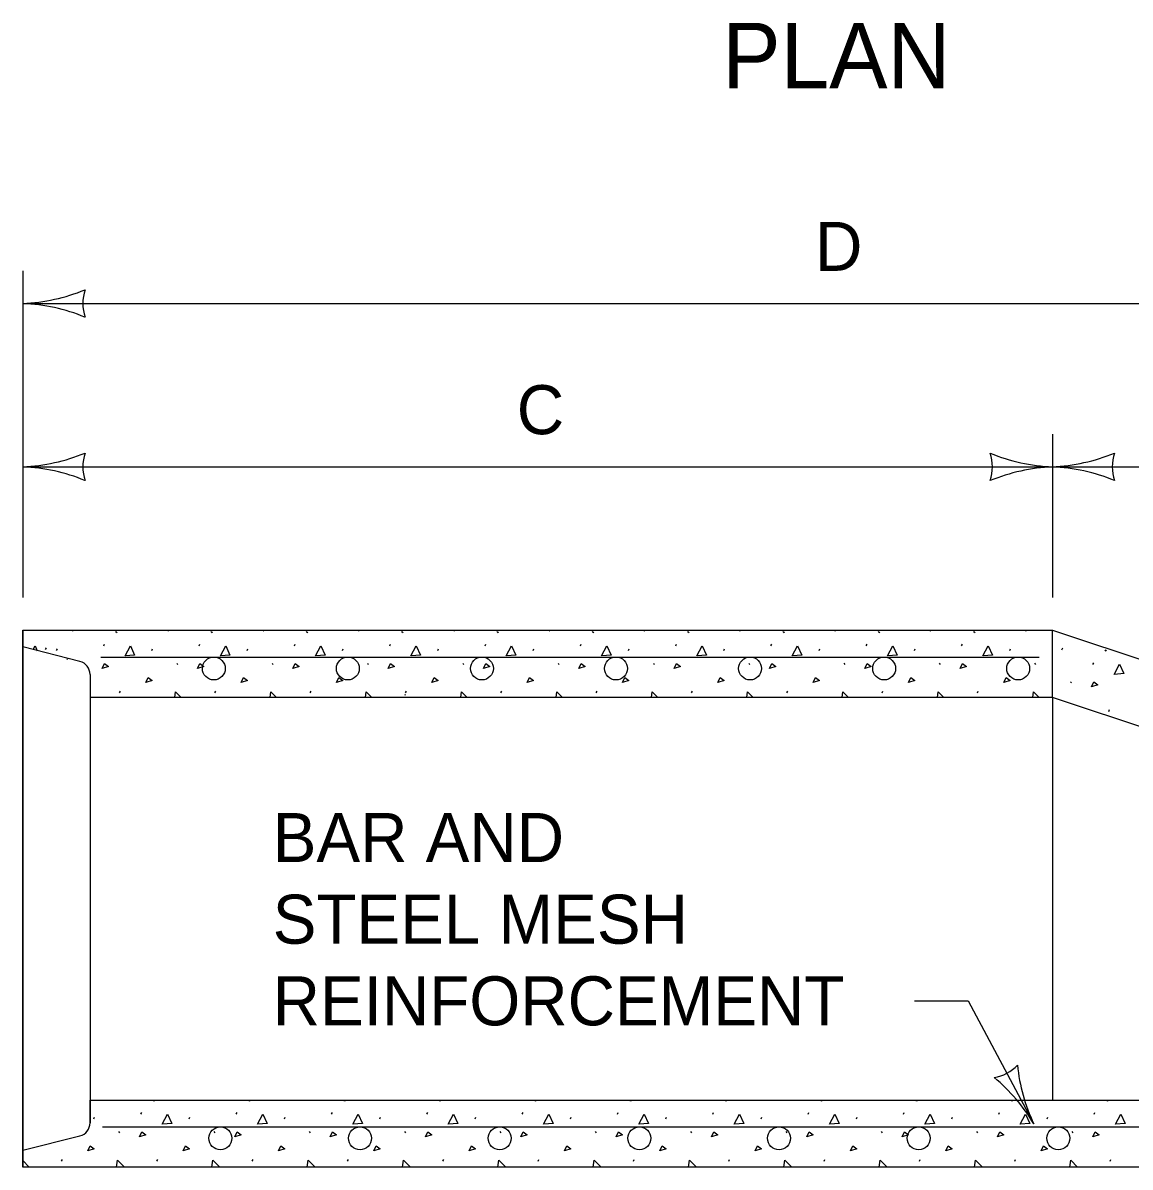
# Model space of a CAD drawing. Extents: x 49991.4 to 50022.1, y 49985 to 50011.4.
# Drawn here: x 50009.608 to 50010.964, y 49995.4 to 49996.801 of the extents above; entities that cross this region are included whole.
import ezdxf

# ---------------------------------------------------------------- set-up
doc = ezdxf.new("R2010")
doc.units = 0
for name, color, linetype in [('Level 1', 7, 'Continuous'), ('Level 2', 7, 'Continuous'), ('Level 3', 7, 'Continuous')]:
    doc.layers.add(name, color=color, linetype=linetype)

msp = doc.modelspace()

# ---------------------------------------------------------------- linework, layer by layer
at = {"layer": 'Level 1'}
for p, q in [((50009.6084, 49996.0573), (50010.8686, 49996.0573)), ((50009.6084, 49996.0573), (50009.6084, 49995.3998)), ((50009.6084, 49995.3998), (50009.6084, 49996.0573)), ((50009.6084, 49995.4204), (50009.6084, 49996.0573)), ((50009.6693, 49996.0561), (50009.6698, 49996.0573)), ((50009.7217, 49996.0561), (50009.7227, 49996.0546)), ((50009.7227, 49996.0555), (50009.7236, 49996.0541)), ((50009.786, 49996.0561), (50009.7865, 49996.0573)), ((50009.8384, 49996.0561), (50009.8394, 49996.0546)), ((50009.8394, 49996.0555), (50009.8403, 49996.0541)), ((50009.9027, 49996.0561), (50009.9032, 49996.0573)), ((50009.9551, 49996.0561), (50009.956, 49996.0546)), ((50009.956, 49996.0555), (50009.957, 49996.0541)), ((50010.0194, 49996.0561), (50010.0199, 49996.0573)), ((50010.0718, 49996.0561), (50010.0727, 49996.0546)), ((50010.0727, 49996.0555), (50010.0737, 49996.0541)), ((50010.1361, 49996.0561), (50010.1366, 49996.0573)), ((50010.1884, 49996.0561), (50010.1894, 49996.0546)), ((50010.1894, 49996.0555), (50010.1904, 49996.0541)), ((50010.2528, 49996.0561), (50010.2533, 49996.0573)), ((50010.3051, 49996.0561), (50010.3061, 49996.0546)), ((50010.3061, 49996.0555), (50010.3071, 49996.0541)), ((50010.3694, 49996.0561), (50010.3699, 49996.0573)), ((50010.4218, 49996.0561), (50010.4228, 49996.0546)), ((50010.4228, 49996.0555), (50010.4238, 49996.0541)), ((50010.4861, 49996.0561), (50010.4866, 49996.0573)), ((50010.5385, 49996.0561), (50010.5395, 49996.0546)), ((50010.5395, 49996.0555), (50010.5405, 49996.0541)), ((50010.6028, 49996.0561), (50010.6033, 49996.0573)), ((50010.6552, 49996.0561), (50010.6562, 49996.0546)), ((50010.6562, 49996.0555), (50010.6572, 49996.0541)), ((50010.7195, 49996.0561), (50010.72, 49996.0573)), ((50010.7719, 49996.0561), (50010.7729, 49996.0546)), ((50010.7729, 49996.0555), (50010.7738, 49996.0541)), ((50010.8362, 49996.0561), (50010.8367, 49996.0573)), ((50010.8686, 49996.0573), (50011.5522, 49995.8295)), ((50010.8686, 49995.975), (50010.8686, 49996.0573)), ((50009.6782, 49996.019), (50009.6084, 49996.0367)), ((50009.6362, 49996.0335), (50009.6372, 49996.0357)), ((50009.6496, 49996.0324), (50009.6506, 49996.0346)), ((50009.7073, 49996.038), (50009.7083, 49996.0402)), ((50009.7663, 49996.0324), (50009.7672, 49996.0346)), ((50009.824, 49996.038), (50009.825, 49996.0402)), ((50009.883, 49996.0324), (50009.8839, 49996.0346)), ((50009.9407, 49996.038), (50009.9417, 49996.0402)), ((50009.9996, 49996.0324), (50010.0006, 49996.0346)), ((50010.0574, 49996.038), (50010.0584, 49996.0402)), ((50010.1163, 49996.0324), (50010.1173, 49996.0346)), ((50010.1741, 49996.038), (50010.175, 49996.0402)), ((50010.233, 49996.0324), (50010.234, 49996.0346)), ((50010.2908, 49996.038), (50010.2917, 49996.0402)), ((50010.3497, 49996.0324), (50010.3507, 49996.0346)), ((50010.4075, 49996.038), (50010.4084, 49996.0402)), ((50010.4664, 49996.0324), (50010.4674, 49996.0346)), ((50010.5241, 49996.038), (50010.5251, 49996.0402)), ((50010.5831, 49996.0324), (50010.5841, 49996.0346)), ((50010.6408, 49996.038), (50010.6418, 49996.0402)), ((50010.6998, 49996.0324), (50010.7008, 49996.0346)), ((50010.7575, 49996.038), (50010.7585, 49996.0402)), ((50010.8165, 49996.0324), (50010.8174, 49996.0346)), ((50010.8803, 49996.0334), (50010.8813, 49996.0356)), ((50010.9327, 49996.0334), (50010.9336, 49996.0319)), ((50010.9336, 49996.0328), (50010.9346, 49996.0314)), ((50009.6778, 49996.0193), (50009.678, 49996.019)), ((50009.7967, 49996.0169), (50009.7977, 49996.0154)), ((50009.9134, 49996.0169), (50009.9144, 49996.0154)), ((50010.0301, 49996.0169), (50010.0311, 49996.0154)), ((50010.1468, 49996.0169), (50010.1478, 49996.0154)), ((50010.2635, 49996.0169), (50010.2645, 49996.0154)), ((50010.3802, 49996.0169), (50010.3811, 49996.0154)), ((50010.4969, 49996.0169), (50010.4978, 49996.0154)), ((50010.6135, 49996.0169), (50010.6145, 49996.0154)), ((50010.7302, 49996.0169), (50010.7312, 49996.0154)), ((50010.8469, 49996.0169), (50010.8479, 49996.0154)), ((50010.9183, 49996.0153), (50010.9193, 49996.0175)), ((50009.6906, 49996.0031), (50009.6906, 49995.454)), ((50010.891, 49995.9941), (50010.892, 49995.9927)), ((50009.7268, 49995.9806), (50009.7278, 49995.9827)), ((50009.8435, 49995.9806), (50009.8445, 49995.9827)), ((50009.9602, 49995.9806), (50009.9612, 49995.9827)), ((50010.0758, 49995.9788), (50010.0765, 49995.9778)), ((50010.0769, 49995.9806), (50010.0778, 49995.9827)), ((50010.1936, 49995.9806), (50010.1945, 49995.9827)), ((50010.3103, 49995.9806), (50010.3112, 49995.9827)), ((50010.4269, 49995.9806), (50010.4279, 49995.9827)), ((50010.5436, 49995.9806), (50010.5446, 49995.9827)), ((50010.6603, 49995.9806), (50010.6613, 49995.9827)), ((50010.777, 49995.9806), (50010.778, 49995.9827)), ((50010.8686, 49995.975), (50009.6906, 49995.975)), ((50011.5634, 49995.7435), (50010.8686, 49995.975)), ((50010.8686, 49995.975), (50010.8686, 49995.4819)), ((50010.9378, 49995.9578), (50010.9387, 49995.96)), ((50009.6906, 49995.4819), (50011.6084, 49995.4819)), ((50009.6906, 49995.454), (50009.6906, 49995.4819)), ((50009.7678, 49995.4819), (50009.7683, 49995.4811)), ((50009.7683, 49995.482), (50009.7692, 49995.4806)), ((50009.8845, 49995.4819), (50009.885, 49995.4811)), ((50009.885, 49995.482), (50009.8859, 49995.4806)), ((50010.0012, 49995.4819), (50010.0017, 49995.4811)), ((50010.0017, 49995.482), (50010.0026, 49995.4806)), ((50010.1178, 49995.4819), (50010.1183, 49995.4811)), ((50010.1183, 49995.482), (50010.1193, 49995.4806)), ((50010.2345, 49995.4819), (50010.235, 49995.4811)), ((50010.235, 49995.482), (50010.236, 49995.4806)), ((50010.3512, 49995.4819), (50010.3517, 49995.4811)), ((50010.3517, 49995.482), (50010.3527, 49995.4806)), ((50010.4679, 49995.4819), (50010.4684, 49995.4811)), ((50010.4684, 49995.482), (50010.4694, 49995.4806)), ((50010.5846, 49995.4819), (50010.5851, 49995.4811)), ((50010.5851, 49995.482), (50010.5861, 49995.4806)), ((50010.7013, 49995.4819), (50010.7018, 49995.4811)), ((50010.7018, 49995.482), (50010.7028, 49995.4806)), ((50010.818, 49995.4819), (50010.8185, 49995.4811)), ((50010.8185, 49995.482), (50010.8195, 49995.4806)), ((50010.9347, 49995.4819), (50010.9352, 49995.4811)), ((50010.9352, 49995.482), (50010.9361, 49995.4806)), ((50009.6952, 49995.4589), (50009.6962, 49995.4611)), ((50009.7529, 49995.4645), (50009.7539, 49995.4667)), ((50009.8119, 49995.4589), (50009.8129, 49995.4611)), ((50009.8696, 49995.4645), (50009.8706, 49995.4667)), ((50009.9286, 49995.4589), (50009.9295, 49995.4611)), ((50009.9863, 49995.4645), (50009.9873, 49995.4667)), ((50010.0453, 49995.4589), (50010.0462, 49995.4611)), ((50010.103, 49995.4645), (50010.104, 49995.4667)), ((50010.1619, 49995.4589), (50010.1629, 49995.4611)), ((50010.2197, 49995.4645), (50010.2207, 49995.4667)), ((50010.2786, 49995.4589), (50010.2796, 49995.4611)), ((50010.3364, 49995.4645), (50010.3373, 49995.4667)), ((50010.3953, 49995.4589), (50010.3963, 49995.4611)), ((50010.4531, 49995.4645), (50010.454, 49995.4667)), ((50010.512, 49995.4589), (50010.513, 49995.4611)), ((50010.5698, 49995.4645), (50010.5707, 49995.4667)), ((50010.6287, 49995.4589), (50010.6297, 49995.4611)), ((50010.6864, 49995.4645), (50010.6874, 49995.4667)), ((50010.7454, 49995.4589), (50010.7464, 49995.4611)), ((50010.8031, 49995.4645), (50010.8041, 49995.4667)), ((50010.8621, 49995.4589), (50010.8631, 49995.4611)), ((50010.9198, 49995.4645), (50010.9208, 49995.4667)), ((50009.6084, 49995.4204), (50009.6782, 49995.4381)), ((50009.7256, 49995.4434), (50009.7266, 49995.4419)), ((50009.8423, 49995.4434), (50009.8433, 49995.4419)), ((50009.959, 49995.4434), (50009.96, 49995.4419)), ((50010.0757, 49995.4434), (50010.0767, 49995.4419)), ((50010.1924, 49995.4434), (50010.1934, 49995.4419)), ((50010.3091, 49995.4434), (50010.3101, 49995.4419)), ((50010.4258, 49995.4434), (50010.4268, 49995.4419)), ((50010.5425, 49995.4434), (50010.5434, 49995.4419)), ((50010.6592, 49995.4434), (50010.6601, 49995.4419)), ((50010.7758, 49995.4434), (50010.7768, 49995.4419)), ((50010.8925, 49995.4434), (50010.8935, 49995.4419)), ((50009.6557, 49995.4071), (50009.6567, 49995.4092)), ((50009.7724, 49995.4071), (50009.7734, 49995.4092)), ((50009.8891, 49995.4071), (50009.8901, 49995.4092)), ((50010.0058, 49995.4071), (50010.0068, 49995.4092)), ((50010.1225, 49995.4071), (50010.1235, 49995.4092)), ((50010.2392, 49995.4071), (50010.2401, 49995.4092)), ((50010.3559, 49995.4071), (50010.3568, 49995.4092)), ((50010.4726, 49995.4071), (50010.4735, 49995.4092)), ((50010.5892, 49995.4071), (50010.5902, 49995.4092)), ((50010.7059, 49995.4071), (50010.7069, 49995.4092)), ((50010.8226, 49995.4071), (50010.8236, 49995.4092)), ((50010.9393, 49995.4071), (50010.9403, 49995.4092)), ((50011.6084, 49995.3998), (50009.6084, 49995.3998))]:
    msp.add_line(p, q, dxfattribs=at)
for points in [[(50009.6208, 49996.0336), (50009.6233, 49996.0383), (50009.626, 49996.0322)], [(50009.7334, 49996.0259), (50009.74, 49996.0383), (50009.7451, 49996.0268), (50009.7336, 49996.0259)], [(50009.8501, 49996.0259), (50009.8567, 49996.0383), (50009.8618, 49996.0268), (50009.8503, 49996.0259)], [(50009.9668, 49996.0259), (50009.9733, 49996.0383), (50009.9785, 49996.0268), (50009.967, 49996.0259)], [(50010.0835, 49996.0259), (50010.09, 49996.0383), (50010.0951, 49996.0268), (50010.0837, 49996.0259)], [(50010.2001, 49996.0259), (50010.2067, 49996.0383), (50010.2118, 49996.0268), (50010.2004, 49996.0259)], [(50010.3168, 49996.0259), (50010.3234, 49996.0383), (50010.3285, 49996.0268), (50010.3171, 49996.0259)], [(50010.4335, 49996.0259), (50010.4401, 49996.0383), (50010.4452, 49996.0268), (50010.4338, 49996.0259)], [(50010.5502, 49996.0259), (50010.5568, 49996.0383), (50010.5619, 49996.0268), (50010.5505, 49996.0259)], [(50010.6669, 49996.0259), (50010.6735, 49996.0383), (50010.6786, 49996.0268), (50010.6671, 49996.0259)], [(50010.7836, 49996.0259), (50010.7902, 49996.0383), (50010.7953, 49996.0268), (50010.7838, 49996.0259)], [(50009.6623, 49996.0213), (50009.6625, 49996.0216)], [(50009.6629, 49996.0213), (50009.6625, 49996.0213)], [(50009.7037, 49996.0243), (50010.8526, 49996.0243)], [(50009.7056, 49996.0105), (50009.7085, 49996.0166), (50009.7134, 49996.013), (50009.7056, 49996.0105)], [(50009.8223, 49996.0105), (50009.8252, 49996.0166), (50009.8301, 49996.013), (50009.8223, 49996.0105)], [(50009.939, 49996.0105), (50009.9419, 49996.0166), (50009.9468, 49996.013), (50009.939, 49996.0105)], [(50010.0557, 49996.0105), (50010.0586, 49996.0166), (50010.0635, 49996.013), (50010.0557, 49996.0105)], [(50010.1724, 49996.0105), (50010.1753, 49996.0166), (50010.1802, 49996.013), (50010.1724, 49996.0105)], [(50010.2891, 49996.0105), (50010.292, 49996.0166), (50010.2969, 49996.013), (50010.2891, 49996.0105)], [(50010.4057, 49996.0105), (50010.4087, 49996.0166), (50010.4135, 49996.013), (50010.4057, 49996.0105)], [(50010.5224, 49996.0105), (50010.5254, 49996.0166), (50010.5302, 49996.013), (50010.5224, 49996.0105)], [(50010.6391, 49996.0105), (50010.642, 49996.0166), (50010.6469, 49996.013), (50010.6391, 49996.0105)], [(50010.7558, 49996.0105), (50010.7587, 49996.0166), (50010.7636, 49996.013), (50010.7558, 49996.0105)], [(50010.9444, 49996.0032), (50010.9509, 49996.0156), (50010.956, 49996.0041), (50010.9446, 49996.0032)], [(50009.759, 49995.9931), (50009.7619, 49995.9992), (50009.7668, 49995.9955), (50009.759, 49995.9931)], [(50009.8757, 49995.9931), (50009.8786, 49995.9992), (50009.8835, 49995.9955), (50009.8757, 49995.9931)], [(50009.9924, 49995.9931), (50009.9953, 49995.9992), (50010.0002, 49995.9955), (50009.9924, 49995.9931)], [(50010.1091, 49995.9931), (50010.112, 49995.9992), (50010.1169, 49995.9955), (50010.1091, 49995.9931)], [(50010.2258, 49995.9931), (50010.2287, 49995.9992), (50010.2336, 49995.9955), (50010.2258, 49995.9931)], [(50010.3425, 49995.9931), (50010.3454, 49995.9992), (50010.3503, 49995.9955), (50010.3425, 49995.9931)], [(50010.4591, 49995.9931), (50010.4621, 49995.9992), (50010.4669, 49995.9955), (50010.4591, 49995.9931)], [(50010.5758, 49995.9931), (50010.5788, 49995.9992), (50010.5836, 49995.9955), (50010.5758, 49995.9931)], [(50010.6925, 49995.9931), (50010.6954, 49995.9992), (50010.7003, 49995.9955), (50010.6925, 49995.9931)], [(50010.8092, 49995.9931), (50010.8121, 49995.9992), (50010.817, 49995.9955), (50010.8092, 49995.9931)], [(50010.9166, 49995.9878), (50010.9195, 49995.9939), (50010.9244, 49995.9902), (50010.9166, 49995.9878)], [(50009.7945, 49995.975), (50009.7954, 49995.982), (50009.8022, 49995.975)], [(50009.9112, 49995.975), (50009.9121, 49995.982), (50009.9189, 49995.975)], [(50010.0278, 49995.975), (50010.0288, 49995.982), (50010.0356, 49995.975)], [(50010.1445, 49995.975), (50010.1455, 49995.982), (50010.1523, 49995.975)], [(50010.2612, 49995.975), (50010.2622, 49995.982), (50010.269, 49995.975)], [(50010.3779, 49995.975), (50010.3788, 49995.982), (50010.3856, 49995.975)], [(50010.4946, 49995.975), (50010.4955, 49995.982), (50010.5023, 49995.975)], [(50010.6113, 49995.975), (50010.6122, 49995.982), (50010.619, 49995.975)], [(50010.728, 49995.975), (50010.7289, 49995.982), (50010.7357, 49995.975)], [(50010.8447, 49995.975), (50010.8456, 49995.982), (50010.8524, 49995.975)], [(50009.779, 49995.4524), (50009.7856, 49995.4648), (50009.7907, 49995.4533), (50009.7792, 49995.4524)], [(50009.8957, 49995.4524), (50009.9023, 49995.4648), (50009.9074, 49995.4533), (50009.8959, 49995.4524)], [(50010.0124, 49995.4524), (50010.019, 49995.4648), (50010.0241, 49995.4533), (50010.0126, 49995.4524)], [(50010.1291, 49995.4524), (50010.1356, 49995.4648), (50010.1408, 49995.4533), (50010.1293, 49995.4524)], [(50010.2458, 49995.4524), (50010.2523, 49995.4648), (50010.2574, 49995.4533), (50010.246, 49995.4524)], [(50010.3624, 49995.4524), (50010.369, 49995.4648), (50010.3741, 49995.4533), (50010.3627, 49995.4524)], [(50010.4791, 49995.4524), (50010.4857, 49995.4648), (50010.4908, 49995.4533), (50010.4794, 49995.4524)], [(50010.5958, 49995.4524), (50010.6024, 49995.4648), (50010.6075, 49995.4533), (50010.5961, 49995.4524)], [(50010.7125, 49995.4524), (50010.7191, 49995.4648), (50010.7242, 49995.4533), (50010.7128, 49995.4524)], [(50010.8292, 49995.4524), (50010.8358, 49995.4648), (50010.8409, 49995.4533), (50010.8294, 49995.4524)], [(50010.9459, 49995.4524), (50010.9525, 49995.4648), (50010.9576, 49995.4533), (50010.9461, 49995.4524)], [(50009.706, 49995.4491), (50011.5866, 49995.4491)], [(50009.7512, 49995.437), (50009.7541, 49995.4431), (50009.759, 49995.4395), (50009.7512, 49995.437)], [(50009.8679, 49995.437), (50009.8708, 49995.4431), (50009.8757, 49995.4395), (50009.8679, 49995.437)], [(50009.9846, 49995.437), (50009.9875, 49995.4431), (50009.9924, 49995.4395), (50009.9846, 49995.437)], [(50010.1013, 49995.437), (50010.1042, 49995.4431), (50010.1091, 49995.4395), (50010.1013, 49995.437)], [(50010.218, 49995.437), (50010.2209, 49995.4431), (50010.2258, 49995.4395), (50010.218, 49995.437)], [(50010.3347, 49995.437), (50010.3376, 49995.4431), (50010.3425, 49995.4395), (50010.3347, 49995.437)], [(50010.4514, 49995.437), (50010.4543, 49995.4431), (50010.4592, 49995.4395), (50010.4514, 49995.437)], [(50010.568, 49995.437), (50010.571, 49995.4431), (50010.5758, 49995.4395), (50010.568, 49995.437)], [(50010.6847, 49995.437), (50010.6877, 49995.4431), (50010.6925, 49995.4395), (50010.6847, 49995.437)], [(50010.8014, 49995.437), (50010.8043, 49995.4431), (50010.8092, 49995.4395), (50010.8014, 49995.437)], [(50010.9181, 49995.437), (50010.921, 49995.4431), (50010.9259, 49995.4395), (50010.9181, 49995.437)], [(50009.6879, 49995.4196), (50009.6909, 49995.4257), (50009.6957, 49995.422), (50009.6879, 49995.4196)], [(50009.8046, 49995.4196), (50009.8075, 49995.4257), (50009.8124, 49995.422), (50009.8046, 49995.4196)], [(50009.9213, 49995.4196), (50009.9242, 49995.4257), (50009.9291, 49995.422), (50009.9213, 49995.4196)], [(50010.038, 49995.4196), (50010.0409, 49995.4257), (50010.0458, 49995.422), (50010.038, 49995.4196)], [(50010.1547, 49995.4196), (50010.1576, 49995.4257), (50010.1625, 49995.422), (50010.1547, 49995.4196)], [(50010.2714, 49995.4196), (50010.2743, 49995.4257), (50010.2792, 49995.422), (50010.2714, 49995.4196)], [(50010.3881, 49995.4196), (50010.391, 49995.4257), (50010.3959, 49995.422), (50010.3881, 49995.4196)], [(50010.5048, 49995.4196), (50010.5077, 49995.4257), (50010.5126, 49995.422), (50010.5048, 49995.4196)], [(50010.6214, 49995.4196), (50010.6244, 49995.4257), (50010.6292, 49995.422), (50010.6214, 49995.4196)], [(50010.7381, 49995.4196), (50010.7411, 49995.4257), (50010.7459, 49995.422), (50010.7381, 49995.4196)], [(50010.8548, 49995.4196), (50010.8577, 49995.4257), (50010.8626, 49995.422), (50010.8548, 49995.4196)], [(50009.6084, 49995.4077), (50009.6161, 49995.3998)], [(50009.7231, 49995.3998), (50009.7243, 49995.4085), (50009.7327, 49995.3998)], [(50009.8398, 49995.3998), (50009.841, 49995.4085), (50009.8494, 49995.3998)], [(50009.9565, 49995.3998), (50009.9577, 49995.4085), (50009.9661, 49995.3998)], [(50010.0732, 49995.3998), (50010.0744, 49995.4085), (50010.0828, 49995.3998)], [(50010.1899, 49995.3998), (50010.1911, 49995.4085), (50010.1995, 49995.3998)], [(50010.3066, 49995.3998), (50010.3078, 49995.4085), (50010.3162, 49995.3998)], [(50010.4233, 49995.3998), (50010.4245, 49995.4085), (50010.4329, 49995.3998)], [(50010.5399, 49995.3998), (50010.5411, 49995.4085), (50010.5496, 49995.3998)], [(50010.6566, 49995.3998), (50010.6578, 49995.4085), (50010.6663, 49995.3998)], [(50010.7733, 49995.3998), (50010.7745, 49995.4085), (50010.783, 49995.3998)], [(50010.89, 49995.3998), (50010.8912, 49995.4085), (50010.8996, 49995.3998)]]:
    msp.add_lwpolyline(points, dxfattribs=at)
for centre in [(50009.8421, 49996.0104), (50010.0062, 49996.0104), (50010.1703, 49996.0104), (50010.3344, 49996.0104), (50010.4986, 49996.0104), (50010.6627, 49996.0104), (50010.8268, 49996.0104), (50009.8502, 49995.4351), (50010.0211, 49995.4351), (50010.1921, 49995.4351), (50010.3631, 49995.4351), (50010.534, 49995.4351), (50010.705, 49995.4351), (50010.8759, 49995.4351)]:
    msp.add_circle(centre, 0.014, dxfattribs=at)
for centre, start, end in [((50009.6742, 49996.003), 0, 75.8703), ((50009.6742, 49995.454), 284.1107, 0)]:
    msp.add_arc(centre, 0.0164, start, end, dxfattribs=at)
at = {"layer": 'Level 3'}
for p, q in [((50009.6084, 49996.4973), (50009.6084, 49996.0973)), ((50009.6084, 49996.4573), (50011.6084, 49996.4573)), ((50010.8686, 49996.2973), (50010.8686, 49996.0973)), ((50009.6084, 49996.2573), (50010.8686, 49996.2573)), ((50010.8686, 49996.2573), (50011.6084, 49996.2573)), ((50010.7, 49995.6034), (50010.7655, 49995.6034)), ((50010.7655, 49995.6034), (50010.846, 49995.4526))]:
    msp.add_line(p, q, dxfattribs=at)
for centre, radius, start, end in [((50009.5969, 49996.69), 0.233, 272.8273, 292.0772), ((50009.7366, 49996.4573), 0.0548, 162.1388, 197.8612), ((50009.5992, 49996.2352), 0.2223, 67.456, 87.6395), ((50009.5969, 49996.49), 0.233, 272.8273, 292.0772), ((50009.7366, 49996.2573), 0.0548, 162.1388, 197.8612), ((50010.8778, 49996.4794), 0.2223, 247.456, 267.6395), ((50010.7404, 49996.2573), 0.0548, 342.1388, 17.8612), ((50010.8571, 49996.49), 0.233, 272.8273, 292.0772), ((50010.9968, 49996.2573), 0.0548, 162.1388, 197.8612), ((50009.5992, 49996.0352), 0.2223, 67.456, 87.6395), ((50010.8801, 49996.0246), 0.233, 92.8273, 112.0772), ((50010.8594, 49996.0352), 0.2223, 67.456, 87.6395), ((50010.7881, 49995.5612), 0.0526, 280.2056, 315.928), ((50011.0383, 49995.5452), 0.2134, 185.5228, 205.7063), ((50010.6541, 49995.3378), 0.2237, 30.8941, 50.144)]:
    msp.add_arc(centre, radius, start, end, dxfattribs=at)

# ---------------------------------------------------------------- texts
at = {"layer": 'Level 2'}
for s, height, p in [('PLAN', 0.08, (50010.4646, 49996.721)), ('D', 0.06, (50010.5781, 49996.4973)), ('C', 0.06, (50010.213, 49996.2973)), ('BAR AND', 0.06, (50009.9142, 49995.7734)), ('STEEL MESH', 0.06, (50009.9142, 49995.6734)), ('REINFORCEMENT', 0.06, (50009.9142, 49995.5734))]:
    msp.add_text(s, height=height, dxfattribs=at).set_placement(p)

doc.saveas('drawing.dxf')
